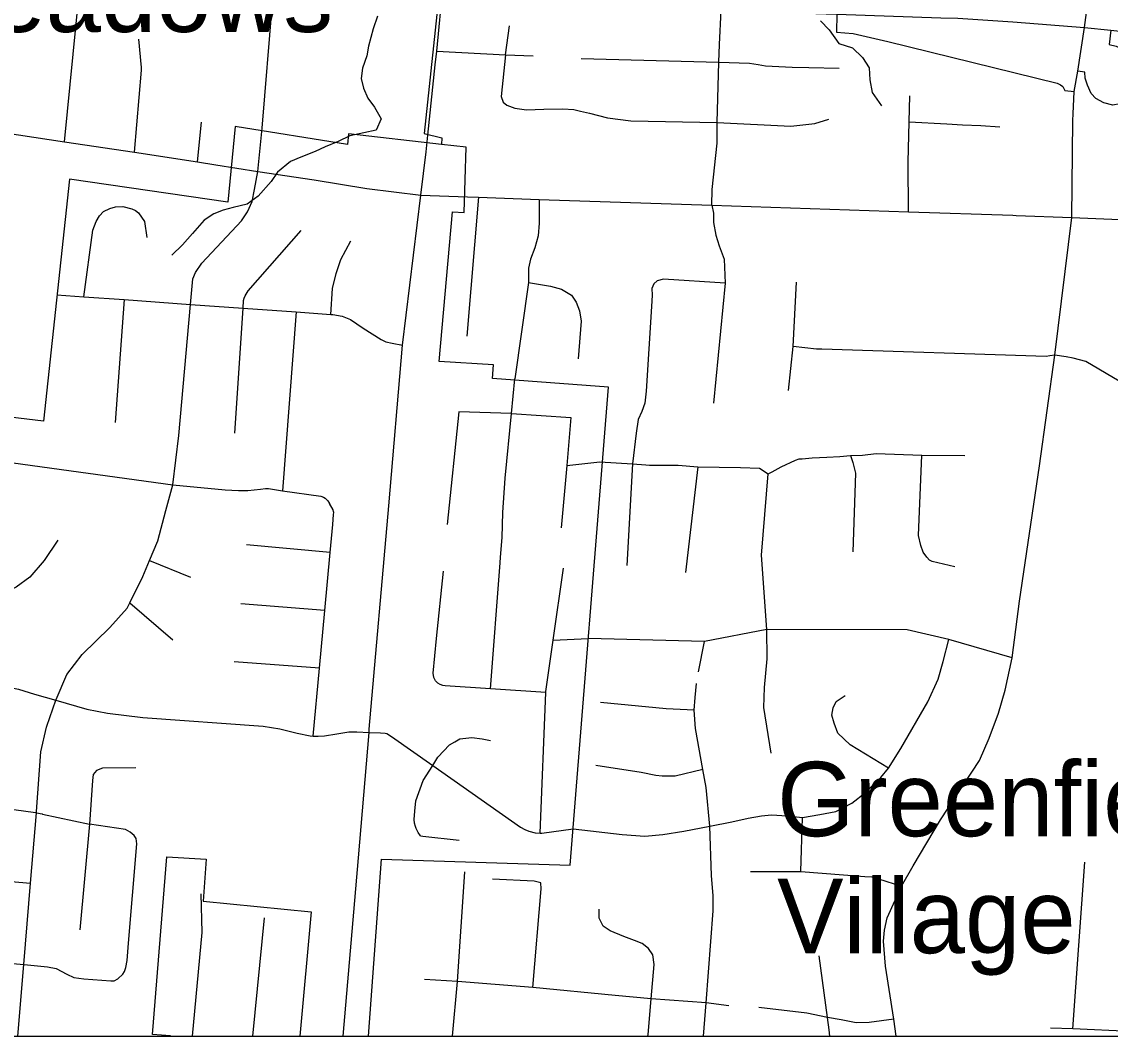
# Model space of a CAD drawing. Extents: x 0 to 34, y 0 to 22.
# Drawn here: x 6.973 to 8.129, y 14.2 to 15.277 of the extents above; entities that cross this region are included whole.
import ezdxf

# ---------------------------------------------------------------- set-up
doc = ezdxf.new("R2010")
doc.units = 0
for name, color, linetype in [('GM_X_City_Street', 7, 'Continuous'), ('GM_X_Corporation', 7, 'Continuous'), ('GM_X_County_Road', 7, 'Continuous'), ('GM_X_Interchange_Ramps', 7, 'Continuous'), ('GM_X_Minor_River', 7, 'Continuous'), ('GM_X_State_Route', 7, 'Continuous'), ('GM_X_Township_Subdivision', 7, 'Continuous'), ('GM_X_Unincorporated_Text', 7, 'Continuous'), ('SH_Data', 7, 'Continuous')]:
    doc.layers.add(name, color=color, linetype=linetype)

msp = doc.modelspace()

# ---------------------------------------------------------------- linework, layer by layer
at = {"layer": 'GM_X_City_Street'}
for points in [[(7.0179, 15.1499), (7.0394, 15.3649), (7.058, 15.5396)], [(7.2281, 15.1642), (7.2388, 15.2975), (7.2482, 15.3705)], [(7.0997, 15.2287), (7.0971, 15.2587)], [(7.0925, 15.1389), (7.0999, 15.226), (7.0997, 15.2287)], [(7.1594, 15.1284), (7.1637, 15.1708)], [(6.9082, 15.1664), (7.0179, 15.1499), (7.0925, 15.1389), (7.1594, 15.1284), (7.1788, 15.1253)], [(7.1332, 14.7855), (7.1364, 14.8117), (7.1396, 14.8378), (7.152, 14.9772), (7.1544, 15.0043), (7.1572, 15.0111), (7.1638, 15.0208), (7.2061, 15.0659), (7.2125, 15.0756), (7.2173, 15.0866), (7.2199, 15.0993), (7.2232, 15.1182), (7.2281, 15.1642)], [(7.3302, 14.3895), (7.3415, 14.5227), (7.3418, 14.5262), (7.3625, 14.7631), (7.3772, 14.9339), (7.3966, 15.093), (7.402, 15.1393), (7.4039, 15.1568)], [(7.1788, 15.1253), (7.2232, 15.1182), (7.2832, 15.1093), (7.3391, 15.1003), (7.3966, 15.093), (7.446, 15.0913)], [(7.0387, 14.9852), (7.0481, 15.056), (7.0518, 15.0652), (7.055, 15.0711), (7.0594, 15.0758), (7.066, 15.079), (7.072, 15.0808), (7.08, 15.0813), (7.0895, 15.0788), (7.0935, 15.0769), (7.0966, 15.0744), (7.1031, 15.0651), (7.1053, 15.0483)], [(7.1991, 14.8403), (7.2077, 14.9732), (7.2082, 14.9814), (7.2088, 14.9837), (7.21, 14.9864), (7.2131, 14.9915), (7.2693, 15.0556)], [(7.3009, 14.9666), (7.3025, 14.9942), (7.3067, 15.01), (7.3117, 15.0247), (7.3222, 15.0445)], [(7.01, 14.9872), (7.0387, 14.9852), (7.0813, 14.9822), (7.152, 14.9772), (7.2077, 14.9732), (7.2642, 14.9692), (7.3009, 14.9666), (7.3032, 14.9664), (7.313, 14.9646), (7.3217, 14.9613), (7.3351, 14.9518), (7.3545, 14.9398), (7.3593, 14.9374), (7.3661, 14.9361), (7.3772, 14.9339)], [(7.0813, 14.9822), (7.0717, 14.8518)], [(7.2642, 14.9692), (7.2494, 14.7793)], [(7.4808, 14.7027), (7.4812, 14.7089), (7.4828, 14.7298), (7.4837, 14.756), (7.486, 14.7928), (7.4927, 14.8613), (7.4964, 14.8981)], [(7.4927, 14.8613), (7.4369, 14.8629), (7.4246, 14.7435)], [(7.4927, 14.8613), (7.556, 14.857), (7.5515, 14.806), (7.5457, 14.7399)], [(6.7143, 14.8571), (6.7624, 14.8487), (6.8557, 14.8325), (6.8662, 14.828), (6.8819, 14.8207), (6.8932, 14.8181), (6.9099, 14.8161), (6.9533, 14.8102), (7.1332, 14.7855), (7.1886, 14.7802), (7.203, 14.7794), (7.2129, 14.7795), (7.2262, 14.781), (7.2315, 14.7815), (7.2346, 14.7815), (7.2494, 14.7793), (7.2903, 14.7734), (7.293, 14.7725), (7.295, 14.7713), (7.2976, 14.7687), (7.2995, 14.7659)], [(7.5515, 14.806), (7.5865, 14.81)], [(6.9993, 14.5292), (7.0087, 14.5568), (7.009, 14.5575), (7.0205, 14.5842), (7.0369, 14.6055), (7.066, 14.6342), (7.0846, 14.6547), (7.0875, 14.6604), (7.1013, 14.6882), (7.1084, 14.7052), (7.1172, 14.7262), (7.1255, 14.7583), (7.1332, 14.7855)], [(7.2823, 14.5188), (7.289, 14.5907), (7.2946, 14.652), (7.3003, 14.7138), (7.3031, 14.7433), (7.3039, 14.754), (7.304, 14.7563), (7.3039, 14.7574), (7.3035, 14.7589), (7.2995, 14.7659)], [(7.011, 14.7269), (6.9963, 14.7053), (6.981, 14.6875), (6.9666, 14.6769), (6.9522, 14.6694), (6.9304, 14.6597), (6.9248, 14.659), (6.9163, 14.6594), (6.9042, 14.662), (6.8953, 14.6676), (6.8855, 14.6792), (6.8605, 14.7093), (6.8266, 14.7502)], [(7.3003, 14.7138), (7.2112, 14.7217)], [(7.1084, 14.7052), (7.152, 14.6874)], [(7.4704, 14.569), (7.4808, 14.7027), (7.4808, 14.7027)], [(7.5231, 14.4157), (7.5292, 14.5651), (7.5293, 14.5662), (7.537, 14.6207), (7.5479, 14.6969)], [(7.4133, 14.6222), (7.4205, 14.6938)], [(7.0875, 14.6604), (7.133, 14.621)], [(7.2946, 14.652), (7.2052, 14.6592)], [(6.4722, 14.646), (6.6567, 14.621), (6.7251, 14.6117), (6.7895, 14.603), (6.7929, 14.6026), (6.9693, 14.5686), (6.9863, 14.5633), (7.0087, 14.5568), (7.0418, 14.5473), (7.0638, 14.5431), (7.1013, 14.5385), (7.2291, 14.5294), (7.2469, 14.5264), (7.2651, 14.5219), (7.2791, 14.5189), (7.2823, 14.5188), (7.2874, 14.5185), (7.2943, 14.519), (7.3072, 14.521), (7.3202, 14.5234), (7.3285, 14.5233), (7.3415, 14.5227)], [(7.5292, 14.5651), (7.4704, 14.569), (7.4223, 14.5722), (7.4198, 14.5726), (7.417, 14.5735), (7.4146, 14.5748), (7.4121, 14.5774), (7.4104, 14.581), (7.4096, 14.5854), (7.4133, 14.6222), (7.4133, 14.6222)], [(7.537, 14.6207), (7.5744, 14.6223)], [(7.289, 14.5907), (7.1984, 14.5975)], [(6.9685, 14.2), (6.9749, 14.2762), (6.982, 14.3624), (6.9882, 14.4373), (6.9883, 14.4386), (6.993, 14.502), (6.9989, 14.5281), (6.9992, 14.5291), (6.9993, 14.5292)], [(7.3415, 14.5227), (7.3536, 14.5222), (7.3586, 14.5219), (7.3604, 14.5214), (7.3653, 14.5183), (7.4091, 14.4876), (7.5024, 14.422), (7.507, 14.4194), (7.5111, 14.4177), (7.5179, 14.4161), (7.5231, 14.4157), (7.5251, 14.4155), (7.5584, 14.4204)], [(7.3962, 14.4128), (7.3937, 14.4163), (7.3915, 14.4206), (7.3908, 14.4227), (7.3897, 14.4263), (7.3895, 14.4303), (7.3903, 14.4391), (7.3913, 14.4498), (7.3989, 14.4716), (7.4091, 14.4876), (7.4146, 14.4964), (7.4271, 14.5094), (7.4325, 14.5128), (7.4378, 14.5157), (7.4508, 14.5173), (7.4618, 14.5159), (7.4705, 14.5139)], [(7.0936, 14.485), (7.0583, 14.4845), (7.0521, 14.4821), (7.0486, 14.478), (7.0476, 14.4716), (7.0447, 14.4253), (7.0342, 14.3131)], [(6.481, 14.4392), (6.7572, 14.3996), (6.8096, 14.3922), (6.8296, 14.3883), (6.8519, 14.3803), (6.8685, 14.3761), (6.895, 14.3699), (6.982, 14.3624)], [(6.9643, 14.4407), (6.9872, 14.4375), (6.9882, 14.4373), (6.9942, 14.436), (6.9946, 14.4359)], [(6.9946, 14.4359), (7.0447, 14.4253)], [(7.0857, 14.2945), (7.095, 14.4044), (7.0941, 14.4101), (7.0919, 14.4132), (7.0878, 14.4168), (7.0829, 14.4196), (7.0447, 14.4253)], [(7.3962, 14.4128), (7.3987, 14.4123), (7.4372, 14.4082)], [(6.9751, 14.2761), (7, 14.2738), (7.009, 14.272), (7.0206, 14.266), (7.0278, 14.2624), (7.0384, 14.2609), (7.0672, 14.2588), (7.0706, 14.2588), (7.0745, 14.261), (7.0799, 14.2658), (7.0818, 14.2687), (7.0832, 14.2729), (7.0845, 14.2805), (7.0857, 14.2943), (7.0857, 14.2945)], [(6.9154, 14.2816), (6.9749, 14.2762), (6.9751, 14.2761)]]:
    msp.add_lwpolyline(points, dxfattribs=at)
at = {"layer": 'GM_X_Corporation'}
for p, q in [((4.7755, 14.2), (7.1307, 14.2)), ((7.268, 14.2), (7.341, 14.2))]:
    msp.add_line(p, q, dxfattribs=at)
for points in [[(6.9605, 15.6641), (7.1222, 15.6381), (7.4375, 15.5883), (7.4066, 15.3204), (7.4172, 15.3188), (7.3999, 15.1585), (7.4188, 15.154), (7.4183, 15.1471), (7.3197, 15.1582), (7.3186, 15.147), (7.1994, 15.166), (7.1914, 15.0856), (7.0234, 15.1102), (6.9956, 14.8531), (6.7125, 14.887)], [(7.341, 14.2), (7.3546, 14.3882), (7.5553, 14.3815), (7.596, 14.8894), (7.4726, 14.8986), (7.4736, 14.913), (7.4159, 14.9164), (7.43, 15.0753), (7.4427, 15.0749), (7.4445, 15.1442), (7.4183, 15.1471), (7.3197, 15.1582), (7.3186, 15.147), (7.1994, 15.166), (7.1914, 15.0856), (7.0234, 15.1102), (6.9956, 14.8531), (6.7125, 14.887)], [(7.1307, 14.2), (7.1307, 14.2003), (7.1116, 14.2017), (7.1268, 14.3906), (7.1685, 14.3879), (7.1652, 14.3434), (7.2799, 14.3322), (7.268, 14.2)]]:
    msp.add_lwpolyline(points, dxfattribs=at)
at = {"layer": 'GM_X_County_Road'}
for points in [[(7.4119, 15.2314), (7.4135, 15.2462), (7.4204, 15.3166), (7.4241, 15.3465), (7.4291, 15.4031)], [(8.0892, 15.1724), (8.0893, 15.1794), (8.0906, 15.2033), (8.0943, 15.2247), (8.1014, 15.2712), (8.1035, 15.2873), (8.1057, 15.3008), (8.119, 15.3989), (8.1194, 15.402)], [(7.4039, 15.1568), (7.4119, 15.2314)], [(7.9014, 14.2), (7.8988, 14.2182), (7.8901, 14.2745), (7.8879, 14.3009), (7.8889, 14.3127), (7.8917, 14.3257), (7.907, 14.3595), (7.9195, 14.3809), (7.9486, 14.4299), (7.9899, 14.4927), (8.0002, 14.5165), (8.0101, 14.5432), (8.0173, 14.5674), (8.0246, 14.602), (8.0323, 14.6619), (8.0535, 14.8057), (8.0698, 14.9231), (8.088, 15.0696), (8.0892, 15.1724)], [(7.446, 15.0913), (7.4578, 15.0909), (7.5222, 15.0884), (7.7055, 15.0825), (7.9145, 15.0754), (8.0252, 15.0718), (8.0288, 15.0717)], [(8.0288, 15.0717), (8.088, 15.0696), (8.1646, 15.0661), (8.1707, 15.0658)], [(7.3141, 14.2), (7.3302, 14.3894), (7.3302, 14.3895)]]:
    msp.add_lwpolyline(points, dxfattribs=at)
at = {"layer": 'GM_X_Interchange_Ramps'}
for points in [[(7.8384, 15.2853), (7.8379, 15.2661), (7.8559, 15.2647), (7.8926, 15.2565), (8.0725, 15.212), (8.076, 15.2105), (8.0783, 15.2085), (8.0807, 15.2042), (8.0906, 15.2033)], [(8.1295, 15.2684), (8.1277, 15.253), (8.135, 15.2513), (8.1463, 15.2462), (8.1549, 15.2388), (8.1596, 15.2321), (8.1623, 15.2259), (8.1627, 15.2161), (8.1596, 15.2064), (8.1541, 15.1986), (8.1475, 15.1931), (8.1389, 15.19), (8.1315, 15.1888), (8.1221, 15.1911), (8.1135, 15.1958), (8.1085, 15.2013), (8.1046, 15.2099), (8.1022, 15.2173), (8.1017, 15.2238), (8.0943, 15.2247)]]:
    msp.add_lwpolyline(points, dxfattribs=at)
at = {"layer": 'GM_X_Minor_River'}
for points in [[(7.3503, 15.2834), (7.3458, 15.2698), (7.3408, 15.2513), (7.339, 15.2411), (7.3345, 15.2282), (7.3331, 15.2169), (7.3355, 15.2069), (7.3402, 15.1962), (7.3472, 15.1865), (7.3545, 15.1741)], [(7.821, 15.2784), (7.8303, 15.2686), (7.8406, 15.2543), (7.8549, 15.2498), (7.8657, 15.2392), (7.8726, 15.2284), (7.8735, 15.2158), (7.8758, 15.2021), (7.8857, 15.1882)], [(7.3545, 15.1741), (7.3489, 15.1621), (7.3359, 15.1594), (7.321, 15.1563), (7.3087, 15.1501), (7.2949, 15.1444), (7.2841, 15.1397), (7.2692, 15.1336), (7.258, 15.1289), (7.2444, 15.1175), (7.2377, 15.1078), (7.2237, 15.0921), (7.2121, 15.0837), (7.1972, 15.0799), (7.1865, 15.0771), (7.1765, 15.0735), (7.1664, 15.0665), (7.1539, 15.0524), (7.1434, 15.0405), (7.1321, 15.0293)]]:
    msp.add_lwpolyline(points, dxfattribs=at)
at = {"layer": 'GM_X_State_Route'}
msp.add_lwpolyline([(7.375, 15.3384), (7.3915, 15.3291), (7.4204, 15.3166), (7.4471, 15.3074), (7.4931, 15.2985), (7.5414, 15.2945), (7.7154, 15.2893), (7.8384, 15.2853), (7.9488, 15.2816), (7.9669, 15.2811), (8.0254, 15.2774), (8.1014, 15.2712), (8.1295, 15.2684), (8.2078, 15.2595), (8.2788, 15.2497), (8.3376, 15.2408), (8.412, 15.227), (8.4869, 15.2128), (8.558, 15.1957), (8.6387, 15.1753)], dxfattribs=at)
at = {"layer": 'GM_X_Township_Subdivision'}
for points in [[(7.7139, 15.2531), (7.7154, 15.2893), (7.7187, 15.3435)], [(7.4866, 15.2421), (7.4908, 15.273)], [(7.7055, 15.0825), (7.7061, 15.0993), (7.7112, 15.1483), (7.7114, 15.1702), (7.7131, 15.2344), (7.7139, 15.2531)], [(7.4135, 15.2462), (7.4866, 15.2421), (7.5159, 15.2412)], [(7.4866, 15.2421), (7.4817, 15.1979), (7.4839, 15.1918), (7.488, 15.1887), (7.4963, 15.1856), (7.5088, 15.1839), (7.527, 15.1845), (7.5472, 15.1848), (7.5589, 15.1842), (7.5662, 15.1824), (7.5758, 15.1803), (7.5949, 15.1754), (7.6195, 15.1721), (7.7114, 15.1702), (7.7897, 15.1665), (7.8152, 15.1692), (7.83, 15.174)], [(7.5667, 15.2384), (7.7131, 15.2344), (7.7456, 15.2333), (7.7547, 15.232), (7.7625, 15.2304), (7.7911, 15.229), (7.8088, 15.2286)], [(7.8088, 15.2286), (7.8408, 15.2279)], [(7.9145, 15.0754), (7.9142, 15.1281), (7.9154, 15.1712), (7.916, 15.1985)], [(7.9154, 15.1712), (7.9552, 15.1689), (7.9718, 15.1678), (7.9914, 15.1672), (8.0117, 15.1656)], [(7.4578, 15.0909), (7.4455, 14.9436)], [(7.5222, 15.0884), (7.5222, 15.0636), (7.5211, 15.05), (7.5175, 15.0373), (7.5129, 15.0253), (7.5109, 15.0156), (7.5108, 15.0004), (7.4964, 14.8981)], [(7.7055, 15.0825), (7.7074, 15.0741), (7.7075, 15.0643), (7.7097, 15.0506), (7.7133, 15.0394), (7.7187, 15.0253), (7.7199, 14.9998), (7.7074, 14.8722)], [(7.5108, 15.0004), (7.5343, 14.9966), (7.5459, 14.9934), (7.5564, 14.9871), (7.5615, 14.9795), (7.5651, 14.9704), (7.5668, 14.9592), (7.5638, 14.9195)], [(7.7199, 14.9998), (7.6542, 15.0038), (7.6475, 15.0021), (7.6439, 14.9989), (7.642, 14.9941), (7.6424, 14.9869), (7.6417, 14.9751), (7.6359, 14.8852), (7.6345, 14.8722), (7.6313, 14.8636), (7.6275, 14.8549), (7.6251, 14.8403), (7.6213, 14.8077), (7.6152, 14.6998)], [(7.787, 14.8856), (7.7921, 14.9323), (7.7956, 15.0009)], [(7.8223, 14.9296), (7.8167, 14.9298), (7.7921, 14.9323)], [(8.0647, 14.9224), (8.0606, 14.9218), (7.8223, 14.9296)], [(8.1382, 14.8955), (8.1029, 14.9166), (8.0895, 14.9202), (8.082, 14.9214), (8.0698, 14.9231), (8.0647, 14.9224)], [(7.6356, 14.8067), (7.6393, 14.8065), (7.67, 14.8065), (7.6906, 14.8048), (7.736, 14.8041), (7.7564, 14.8031), (7.7655, 14.7971), (7.7696, 14.7993), (7.7792, 14.8045), (7.7945, 14.8119), (7.7985, 14.813), (7.8014, 14.8132), (7.8123, 14.8143), (7.8276, 14.8151), (7.8417, 14.8158), (7.8528, 14.8167), (7.8656, 14.817), (7.8802, 14.8187), (7.9288, 14.8172), (7.9743, 14.8166)], [(7.8528, 14.8167), (7.8555, 14.8093), (7.8581, 14.7981), (7.8555, 14.7143)], [(7.9638, 14.6983), (7.9395, 14.7041), (7.9369, 14.7056), (7.9341, 14.7088), (7.9301, 14.7142), (7.9277, 14.7211), (7.9253, 14.7318), (7.9288, 14.8172)], [(7.5865, 14.81), (7.6213, 14.8077), (7.6356, 14.8067)], [(7.6906, 14.8048), (7.6776, 14.6925)], [(7.7688, 14.5006), (7.7609, 14.5492), (7.7616, 14.5702), (7.7643, 14.6006), (7.7641, 14.6318), (7.7583, 14.711), (7.7655, 14.7971)], [(8.0246, 14.602), (7.9575, 14.6214), (7.9132, 14.6317), (7.7641, 14.6318), (7.6978, 14.6193), (7.5744, 14.6223)], [(7.5584, 14.4204), (7.6102, 14.4144), (7.6345, 14.4124), (7.6536, 14.4142), (7.6758, 14.4178), (7.7036, 14.423), (7.7269, 14.4278), (7.7443, 14.4317), (7.7583, 14.434), (7.7691, 14.4352), (7.7857, 14.4342), (7.802, 14.4324), (7.8202, 14.4353), (7.8373, 14.4386), (7.8542, 14.4475), (7.8687, 14.459), (7.8853, 14.4746), (7.8933, 14.4848), (7.9063, 14.5055), (7.9349, 14.5551), (7.9459, 14.5791), (7.9515, 14.598), (7.9575, 14.6214)], [(7.6916, 14.5869), (7.6978, 14.6193)], [(7.6966, 14.2), (7.6996, 14.2353), (7.7072, 14.333), (7.707, 14.3491), (7.7052, 14.3708), (7.7036, 14.423), (7.6997, 14.4643), (7.6959, 14.4832), (7.6882, 14.5269), (7.6868, 14.5463), (7.688, 14.5598), (7.6892, 14.5747)], [(7.8933, 14.4848), (7.8526, 14.5093), (7.8396, 14.5219), (7.8355, 14.5323), (7.8332, 14.541), (7.8345, 14.5487), (7.8378, 14.5556), (7.8473, 14.562)], [(7.6868, 14.5463), (7.6572, 14.5476), (7.5875, 14.5543)], [(7.6959, 14.4832), (7.6666, 14.4761), (7.6528, 14.4761), (7.6461, 14.4769), (7.6304, 14.48), (7.5824, 14.4876)], [(7.8, 14.3749), (7.802, 14.4324)], [(8.0892, 14.2077), (8.1017, 14.385)], [(7.4301, 14.2), (7.4353, 14.2582), (7.4433, 14.3745)], [(7.7467, 14.3749), (7.8, 14.3749), (7.8681, 14.3696), (7.8757, 14.3694), (7.8828, 14.3672), (7.907, 14.3595)], [(7.5153, 14.2517), (7.5244, 14.3564), (7.5241, 14.3628), (7.5169, 14.3648), (7.4727, 14.3667)], [(7.1539, 14.2), (7.1644, 14.31), (7.163, 14.3513)], [(7.218, 14.2), (7.2303, 14.3256)], [(7.6376, 14.2), (7.6381, 14.202), (7.641, 14.2396), (7.6445, 14.2762), (7.6429, 14.2864), (7.6383, 14.293), (7.6317, 14.2985), (7.6234, 14.3018), (7.6122, 14.3059), (7.5975, 14.312), (7.5903, 14.317), (7.5861, 14.3253), (7.5861, 14.3348)], [(7.8311, 14.2), (7.8303, 14.2067), (7.8286, 14.2199), (7.8196, 14.2852)], [(7.7236, 14.2324), (7.6996, 14.2353), (7.641, 14.2396), (7.6029, 14.2434), (7.5153, 14.2517), (7.4353, 14.2582), (7.4003, 14.2604)], [(7.8988, 14.2182), (7.8728, 14.2145), (7.8591, 14.2141), (7.8431, 14.2174), (7.8286, 14.2199), (7.8065, 14.2244), (7.7555, 14.2306)], [(8.2622, 14.2), (8.2604, 14.2004), (8.2124, 14.2024), (8.1505, 14.2051), (8.0892, 14.2077), (8.0652, 14.2087)]]:
    msp.add_lwpolyline(points, dxfattribs=at)
at = {"layer": 'SH_Data'}
msp.add_line((2, 14.2), (8.8, 14.2), dxfattribs=at)

# ---------------------------------------------------------------- texts
at = {"layer": 'GM_X_Unincorporated_Text'}
for s, height, p in [('Spring Meadows', 0.078977, (6.5167, 15.2665)), ('Greenfield', 0.07898, (7.775, 14.4124)), ('Village', 0.07898, (7.775, 14.2882))]:
    msp.add_text(s, height=height, rotation=0, dxfattribs=at).set_placement(p)

doc.saveas('drawing.dxf')
